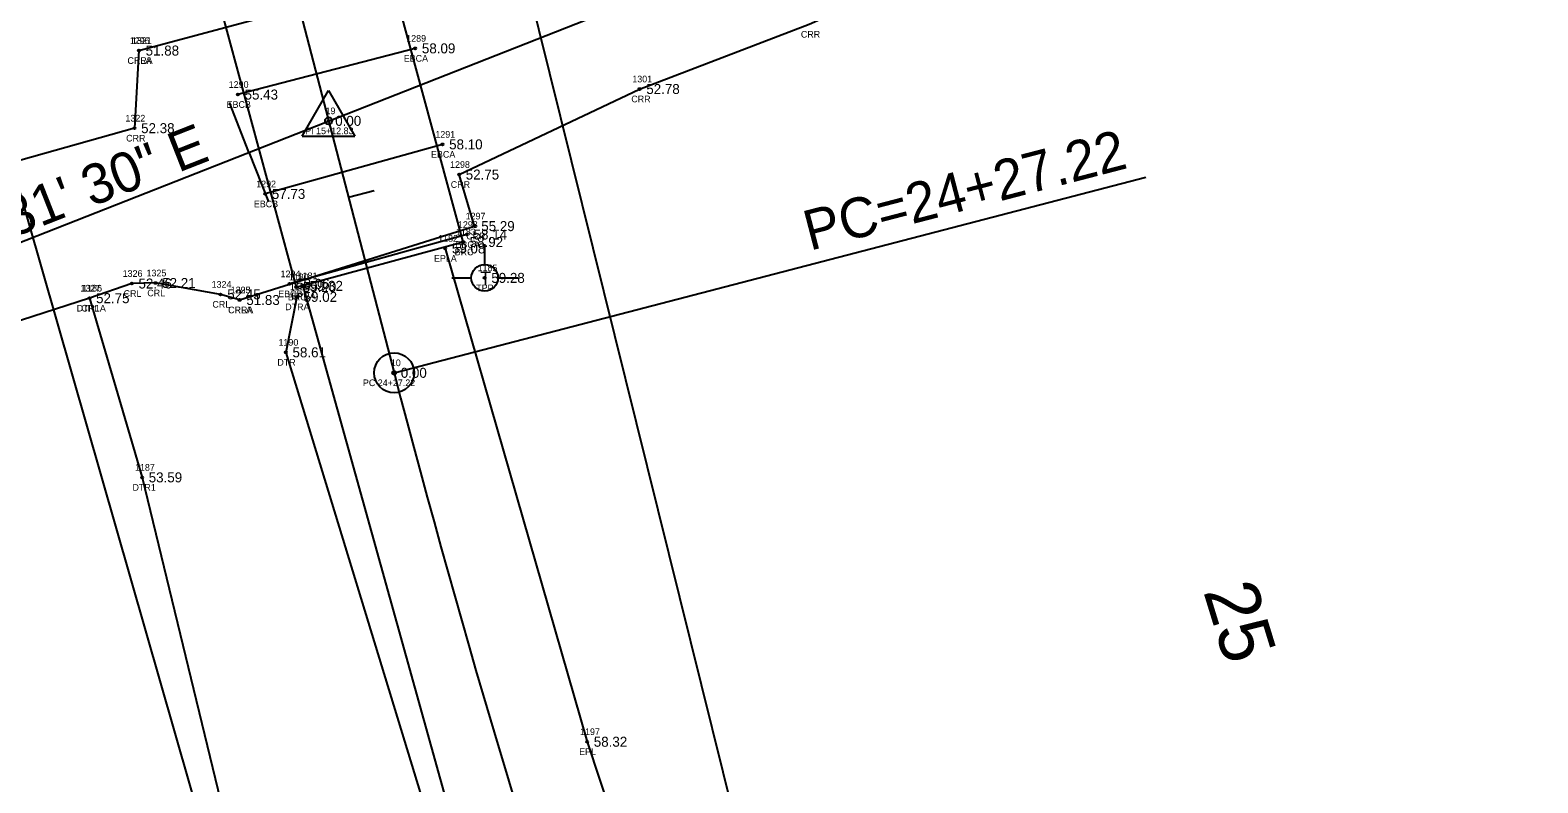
# Model space of a CAD drawing. Extents: x 2396531 to 2397633, y 770203 to 772837.
# Drawn here: x 2397010.1 to 2397236.4, y 771283.5 to 771396.5 of the extents above; entities that cross this region are included whole.
import ezdxf

# ---------------------------------------------------------------- set-up
doc = ezdxf.new("R2010")
doc.units = 0
for name, color, linetype in [('RD_EX_Bridge', 7, 'Continuous'), ('RD_EX_Bridge_txCode', 7, 'Continuous'), ('RD_EX_H2O', 7, 'Continuous'), ('RD_EX_H2O_txCode', 7, 'Continuous'), ('RD_EX_Road', 7, 'Continuous'), ('RD_EX_Road_txCode', 7, 'Continuous'), ('RD_EX_TX_Bridge_ELEV', 7, 'Continuous'), ('RD_EX_TX_H2O_ELEV', 7, 'Continuous'), ('RD_EX_TX_Road_ELEV', 7, 'Continuous'), ('RD_EX_TX_UT_ELEV', 7, 'Continuous'), ('RD_EX_UT', 7, 'Continuous'), ('RD_EX_UT_txCode', 7, 'Continuous'), ('RD_EX_VEG', 7, 'Continuous'), ('RD_HC_Cl', 7, 'Continuous'), ('RD_HC_Data', 7, 'Continuous'), ('RD_HC_Data_Tic', 7, 'Continuous'), ('RD_HC_Survey_ELEV', 7, 'Continuous'), ('RD_HC_TX_Sta50', 7, 'Continuous'), ('RD_HC_txCode', 7, 'Continuous'), ('RD_SMD_Locator', 7, 'Continuous')]:
    doc.layers.add(name, color=color, linetype=linetype)

msp = doc.modelspace()

# ---------------------------------------------------------------- linework, layer by layer
at = {"layer": 'RD_EX_Bridge'}
for p, q in [((2397067.87, 771393.72), (2397041.26, 771386.79)), ((2397071.96, 771379.31), (2397045.35, 771371.87)), ((2397075.63, 771365.77), (2397049, 771358.37))]:
    msp.add_line(p, q, dxfattribs=at)
msp.add_lwpolyline([(2397063.31, 771408), (2397038.31, 771401.16), (2397050, 771357.89), (2397075.04, 771364.66), (2397063.31, 771408)], dxfattribs=at)
at = {"layer": 'RD_EX_H2O'}
for points in [[(2397026.41, 771393.39), (2397070.16, 771405.14), (2397085.18, 771412.94), (2397115.64, 771424.52), (2397174.69, 771450.34), (2397230.25, 771466.48), (2397283.24, 771491.48), (2397342.91, 771519.42), (2397408.89, 771536.24), (2397447.46, 771546.47), (2397469.5, 771549.6), (2397497.19, 771541.27), (2397541.1, 771500.79)], [(2397041.52, 771355.95), (2397076.78, 771367.04), (2397074.45, 771374.78), (2397101.55, 771387.62), (2397127, 771397.33), (2397184.13, 771422.52), (2397239.58, 771440.33), (2397295.12, 771461.42), (2397353.86, 771487.36), (2397417.93, 771512.91), (2397437.51, 771516.93), (2397483.94, 771516.4), (2397526.36, 771480.62)], [(2397026.41, 771393.39), (2397025.73, 771381.74), (2396981.24, 771369.21), (2396933.35, 771351.16), (2396867.1, 771327.21), (2396805.16, 771301.5), (2396726.77, 771268.25), (2396662.72, 771245.88), (2396570.19, 771208.11)], [(2397041.52, 771355.95), (2397038.66, 771356.79), (2397028.89, 771358.5), (2397025.33, 771358.42), (2397018.97, 771356.22), (2396990.02, 771346.89), (2396942.55, 771327.39), (2396877.94, 771304.58), (2396814.23, 771281.47), (2396733.01, 771246.09), (2396670.48, 771223.24), (2396582.44, 771186.21)], [(2397018.97, 771356.22), (2397026.87, 771329.32), (2397040.31, 771274), (2397053.31, 771225.45), (2397046.53, 771217.12), (2397064.09, 771222.58)], [(2397050.12, 771356.42), (2397048.45, 771348.09), (2397069.72, 771278.43), (2397081.62, 771237.82), (2397079.7, 771231.53), (2397072.3, 771225.91), (2397064.09, 771222.58)]]:
    msp.add_lwpolyline(points, dxfattribs=at)
at = {"layer": 'RD_EX_Road'}
for points in [[(2397072.37, 771363.69), (2397093.67, 771289.64), (2397115.94, 771222.21), (2397113.76, 771228.75)], [(2397051, 771358.07), (2397072.97, 771279.15), (2397086.26, 771238.89), (2397093.16, 771212.62)]]:
    msp.add_lwpolyline(points, dxfattribs=at)
at = {"layer": 'RD_EX_UT'}
for p, q in [((2397078.29, 771364.33), (2397078.29, 771361.27)), ((2397073.36, 771359.28), (2397076.29, 771359.28)), ((2397080.29, 771359.28), (2397083.36, 771359.28))]:
    msp.add_line(p, q, dxfattribs=at)
msp.add_circle((2397078.29, 771359.27), 2, dxfattribs=at)
at = {"layer": 'RD_EX_VEG'}
for points in [[(2396666.35, 772324.52), (2396746.5, 772348.13), (2396878.43, 771953.6), (2396907.83, 771806.94), (2396910.04, 771736.08), (2396945.43, 771592.11), (2397049.51, 771229.15), (2396980.16, 771221.67)], [(2397137.17, 771710.16), (2397010.6, 771680.28), (2397078.29, 771429.37), (2397127.02, 771232.69), (2397127.02, 771232.69), (2397166.52, 771123.83), (2397178.02, 771098.29), (2397254.06, 771102.5)]]:
    msp.add_lwpolyline(points, dxfattribs=at)
at = {"layer": 'RD_HC_Cl'}
for p, q in [((2396987, 771643.49), (2397064.7, 771345.02)), ((2396577.63, 771195.09), (2397449.32, 771538.02))]:
    msp.add_line(p, q, dxfattribs=at)
msp.add_arc((2398682.18, 771766.08), 1671.39, 194.59125, 211.50817, dxfattribs=at)
at = {"layer": 'RD_HC_Data'}
for p, q in [((2397050.89, 771380.54), (2397054.86, 771387.42)), ((2397054.86, 771387.42), (2397058.83, 771380.54)), ((2397050.89, 771380.54), (2397058.83, 771380.54)), ((2397064.7, 771345.02), (2397177.51, 771374.38))]:
    msp.add_line(p, q, dxfattribs=at)
for centre, radius in [((2397054.86, 771382.84), 0.529), ((2397064.7, 771345.02), 3), ((2397064.7, 771345.02), 0.282)]:
    msp.add_circle(centre, radius, dxfattribs=at)
at = {"layer": 'RD_HC_Data_Tic'}
for p, q in [((2397042.92, 771378.14), (2397039.99, 771385.58)), ((2397042.92, 771378.14), (2397045.84, 771370.69)), ((2397057.84, 771371.36), (2397061.72, 771372.37))]:
    msp.add_line(p, q, dxfattribs=at)
at = {"layer": 'RD_SMD_Locator'}
for centre in [(2397026.41, 771393.39), (2397026.41, 771393.39), (2397067.87, 771393.72), (2397101.55, 771387.62), (2397041.26, 771386.79), (2397025.73, 771381.74), (2397054.86, 771382.84), (2397071.96, 771379.31), (2397074.45, 771374.78), (2397045.35, 771371.87), (2397075.63, 771365.77), (2397076.78, 771367.04), (2397072.37, 771363.69), (2397075.04, 771364.66), (2397025.33, 771358.42), (2397028.89, 771358.5), (2397049, 771358.37), (2397051, 771358.07), (2397078.29, 771359.27), (2397018.97, 771356.22), (2397018.97, 771356.22), (2397038.66, 771356.79), (2397041.52, 771355.95), (2397041.52, 771355.95), (2397050, 771357.89), (2397050.12, 771356.42), (2397048.45, 771348.09), (2397064.7, 771345.02), (2397026.87, 771329.32), (2397093.67, 771289.64)]:
    msp.add_circle(centre, 0.15, dxfattribs=at)

# ---------------------------------------------------------------- texts
at = {"layer": 'RD_EX_Bridge_txCode'}
for s, p in [('1289', (2397066.52, 771394.72)), ('EBCA', (2397066.15, 771391.72)), ('1290', (2397039.88, 771387.79)), ('EBCB', (2397039.56, 771384.79)), ('1291', (2397070.89, 771380.31)), ('EBCA', (2397070.24, 771377.31)), ('1292', (2397044, 771372.87)), ('EBCB', (2397043.65, 771369.87)), ('1293', (2397074.28, 771366.77)), ('1183', (2397073.98, 771365.66)), ('BRC', (2397073.79, 771362.66)), ('EBCA', (2397073.91, 771363.77)), ('1294', (2397047.66, 771359.37)), ('1180', (2397048.9, 771358.89)), ('EBCB', (2397047.3, 771356.37)), ('BRC', (2397048.75, 771355.89))]:
    msp.add_text(s, height=1, dxfattribs=at).set_placement(p)
at = {"layer": 'RD_EX_H2O_txCode'}
for s, p in [('1296', (2397025.04, 771394.39)), ('1321', (2397025.34, 771394.39)), ('CRR', (2397125.75, 771395.33)), ('CRRA', (2397024.67, 771391.39)), ('CRLA', (2397024.69, 771391.39)), ('1301', (2397100.45, 771388.62)), ('CRR', (2397100.3, 771385.62)), ('1322', (2397024.38, 771382.74)), ('CRR', (2397024.48, 771379.74)), ('1298', (2397073.1, 771375.78)), ('CRR', (2397073.2, 771372.78)), ('1297', (2397075.43, 771368.04)), ('CRR', (2397075.53, 771365.04)), ('1325', (2397027.54, 771359.5)), ('1327', (2397017.63, 771357.22)), ('1186', (2397017.89, 771357.22)), ('1326', (2397023.96, 771359.42)), ('1324', (2397037.31, 771357.79)), ('1189', (2397049.05, 771357.42)), ('CRL', (2397024.1, 771356.42)), ('CRL', (2397027.66, 771356.5)), ('1295', (2397040.17, 771356.95)), ('1323', (2397040.17, 771356.95)), ('DTR1A', (2397017.05, 771354.22)), ('CRL', (2397017.75, 771354.22)), ('CRL', (2397037.43, 771354.79)), ('CRRA', (2397039.78, 771353.95)), ('CRLA', (2397039.8, 771353.95)), ('DTRA', (2397048.36, 771354.42)), ('1190', (2397047.35, 771349.09)), ('DTR', (2397047.18, 771346.09)), ('1187', (2397025.81, 771330.32)), ('DTR1', (2397025.44, 771327.32))]:
    msp.add_text(s, height=1, dxfattribs=at).set_placement(p)
at = {"layer": 'RD_EX_Road_txCode'}
for s, p in [('1182', (2397071.31, 771364.69)), ('EPLA', (2397070.68, 771361.69)), ('1181', (2397050.22, 771359.07)), ('EPRA', (2397049.28, 771356.07)), ('1197', (2397092.61, 771290.64)), ('EPL', (2397092.47, 771287.64))]:
    msp.add_text(s, height=1, dxfattribs=at).set_placement(p)
at = {"layer": 'RD_EX_TX_Bridge_ELEV'}
for s, p in [('58.09', (2397068.87, 771392.97)), ('55.43', (2397042.26, 771386.04)), ('58.10', (2397072.96, 771378.56)), ('57.73', (2397046.35, 771371.12)), ('58.92', (2397076.04, 771363.91)), ('58.14', (2397076.63, 771365.02)), ('58.06', (2397050, 771357.62)), ('59.20', (2397051, 771357.14))]:
    msp.add_text(s, height=1.5, dxfattribs=at).set_placement(p)
at = {"layer": 'RD_EX_TX_H2O_ELEV'}
for s, p in [('51.88', (2397027.41, 771392.64)), ('51.88', (2397027.41, 771392.64)), ('52.78', (2397102.55, 771386.87)), ('52.38', (2397026.73, 771380.99)), ('52.75', (2397075.45, 771374.03)), ('55.29', (2397077.78, 771366.29)), ('52.46', (2397026.33, 771357.67)), ('52.21', (2397029.89, 771357.75)), ('52.75', (2397019.97, 771355.47)), ('52.75', (2397019.97, 771355.47)), ('52.45', (2397039.66, 771356.04)), ('51.83', (2397042.52, 771355.2)), ('51.83', (2397042.52, 771355.2)), ('59.02', (2397051.12, 771355.67)), ('58.61', (2397049.45, 771347.34)), ('53.59', (2397027.87, 771328.57))]:
    msp.add_text(s, height=1.5, dxfattribs=at).set_placement(p)
at = {"layer": 'RD_EX_TX_Road_ELEV'}
for s, p in [('59.08', (2397073.37, 771362.94)), ('59.32', (2397052, 771357.32)), ('58.32', (2397094.67, 771288.89))]:
    msp.add_text(s, height=1.5, dxfattribs=at).set_placement(p)
at = {"layer": 'RD_EX_TX_UT_ELEV'}
msp.add_text('59.28', height=1.5, dxfattribs=at).set_placement((2397079.29, 771358.52))
at = {"layer": 'RD_EX_UT'}
msp.add_text('T', height=2, dxfattribs=at).set_placement((2397077.62, 771358.22))
at = {"layer": 'RD_EX_UT_txCode'}
for s, p in [('1185', (2397077.23, 771360.27)), ('TPP', (2397077.02, 771357.27))]:
    msp.add_text(s, height=1, dxfattribs=at).set_placement(p)
at = {"layer": 'RD_HC_Data'}
for s, rotation, p in [('N 68%%d 31\' 30" E', 21.4751, (2396986.62, 771357.06)), ('PC=24+27.22', 14.5913, (2397127.1, 771363.33))]:
    msp.add_text(s, height=6, rotation=rotation, dxfattribs=at).set_placement(p)
at = {"layer": 'RD_HC_Survey_ELEV'}
for p in [(2397055.86, 771382.09), (2397065.7, 771344.27)]:
    msp.add_text('0.00', height=1.5, dxfattribs=at).set_placement(p)
at = {"layer": 'RD_HC_TX_Sta50'}
msp.add_text('25', height=8, rotation=287.0862, dxfattribs=at).set_placement((2397186.11, 771312.24))
at = {"layer": 'RD_HC_txCode'}
for s, p in [('19', (2397054.41, 771383.84)), ('PI 15+12.83', (2397051.36, 771380.84)), ('10', (2397064.21, 771346.02)), ('PC 24+27.22', (2397060.02, 771343.02))]:
    msp.add_text(s, height=1, dxfattribs=at).set_placement(p)

doc.saveas('drawing.dxf')
